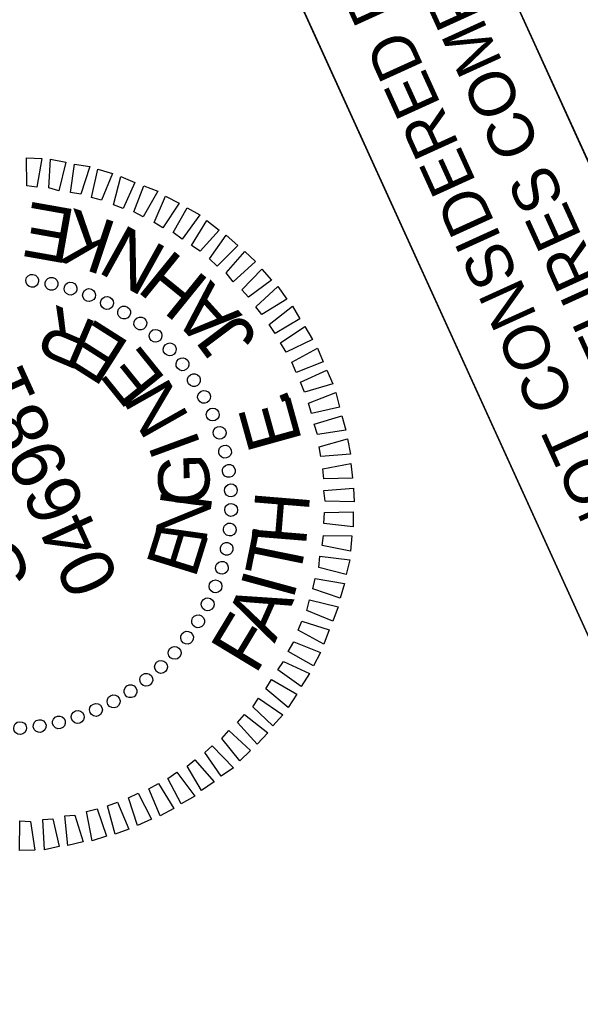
# Model space of a CAD drawing. Extents: x 2096093 to 2099001, y 683546 to 685907.
# Drawn here: x 2097494 to 2097556.6, y 685362.9 to 685471.3 of the extents above; entities that cross this region are included whole.
import ezdxf

# ---------------------------------------------------------------- set-up
doc = ezdxf.new("R2010")
doc.units = 0
for name, color, linetype in [('Old_Level_2', 7, 'Continuous'), ('Sheet Block Title CELL', 7, 'Continuous'), ('Sheet PE Seal Cell', 7, 'Continuous'), ('Sheet Sticker Exception Certification CELL', 7, 'Continuous')]:
    doc.layers.add(name, color=color, linetype=linetype)

msp = doc.modelspace()

# ---------------------------------------------------------------- linework, layer by layer
at = {"layer": 'Old_Level_2'}
msp.add_lwpolyline([(2097478.08, 685308.03), (2097400.68, 685478.2), (2097502.07, 685524.32), (2097579.47, 685354.15)], close=True, dxfattribs=at)
msp.add_lwpolyline([(2097478.08, 685308.03), (2097400.68, 685478.2), (2097502.07, 685524.32), (2097579.47, 685354.15)], close=True, dxfattribs=at)
at = {"layer": 'Sheet Block Title CELL'}
msp.add_lwpolyline([(2097599.44, 685363.23), (2097522.11, 685533.24), (2097544.43, 685543.38), (2097621.75, 685373.38)], close=True, dxfattribs=at)
at = {"layer": 'Sheet PE Seal Cell'}
for p, q in [((2097495.43, 685442.18), (2097495.43, 685442.18)), ((2097497.58, 685441.79), (2097497.58, 685441.79)), ((2097499.73, 685441.29), (2097499.73, 685441.29)), ((2097501.77, 685440.56), (2097501.77, 685440.56)), ((2097503.81, 685439.68), (2097503.81, 685439.68)), ((2097505.68, 685438.61), (2097505.68, 685438.61)), ((2097507.51, 685437.35), (2097507.51, 685437.35)), ((2097509.23, 685435.99), (2097509.23, 685435.99)), ((2097510.78, 685434.5), (2097510.78, 685434.5)), ((2097512.2, 685432.84), (2097512.2, 685432.84)), ((2097513.48, 685431), (2097513.48, 685431)), ((2097514.64, 685429.17), (2097514.64, 685429.17)), ((2097515.59, 685427.19), (2097515.59, 685427.19)), ((2097516.37, 685425.12), (2097516.37, 685425.12)), ((2097516.94, 685423.02), (2097516.94, 685423.02)), ((2097517.4, 685420.92), (2097517.4, 685420.92)), ((2097517.63, 685418.72), (2097517.63, 685418.72)), ((2097517.64, 685416.53), (2097517.64, 685416.53)), ((2097517.54, 685414.34), (2097517.54, 685414.34)), ((2097517.15, 685412.18), (2097517.15, 685412.18)), ((2097516.64, 685410.03), (2097516.64, 685410.03)), ((2097515.92, 685408), (2097515.92, 685408)), ((2097515.04, 685405.95), (2097515.04, 685405.95)), ((2097513.96, 685404.09), (2097513.96, 685404.09)), ((2097512.71, 685402.26), (2097512.71, 685402.26)), ((2097511.35, 685400.54), (2097511.35, 685400.54)), ((2097509.86, 685398.98), (2097509.86, 685398.98)), ((2097508.19, 685397.57), (2097508.19, 685397.57)), ((2097506.36, 685396.29), (2097506.36, 685396.29)), ((2097504.53, 685395.13), (2097504.53, 685395.13)), ((2097502.54, 685394.17), (2097502.54, 685394.17)), ((2097498.38, 685392.83), (2097498.38, 685392.83)), ((2097500.48, 685393.4), (2097500.48, 685393.4)), ((2097494.08, 685392.13), (2097494.08, 685392.13)), ((2097496.28, 685392.37), (2097496.28, 685392.37))]:
    msp.add_line(p, q, dxfattribs=at)
for points in [[(2097494.81, 685452.72), (2097494.77, 685455.84), (2097496.49, 685455.79), (2097495.92, 685452.57)], [(2097497.26, 685452.52), (2097497.47, 685455.69), (2097499.16, 685455.36), (2097498.41, 685452.17)], [(2097499.7, 685451.98), (2097500.13, 685455.15), (2097501.85, 685454.88), (2097500.84, 685451.79)], [(2097502.05, 685451.41), (2097502.75, 685454.58), (2097504.39, 685454.12), (2097503.16, 685451.14)], [(2097504.51, 685450.6), (2097505.32, 685453.77), (2097506.88, 685453.11), (2097505.57, 685450.2)], [(2097506.78, 685449.82), (2097507.88, 685452.73), (2097509.46, 685452.14), (2097507.81, 685449.25)], [(2097509.02, 685448.64), (2097510.32, 685451.59), (2097511.83, 685450.8), (2097510.01, 685448.05)], [(2097511.17, 685447.53), (2097512.73, 685450.27), (2097514.13, 685449.48), (2097512.18, 685446.78)], [(2097513.22, 685446.05), (2097514.91, 685448.85), (2097516.28, 685447.77), (2097514.16, 685445.43)], [(2097515.21, 685444.59), (2097517.09, 685447.2), (2097518.37, 685446.08), (2097516.07, 685443.77)], [(2097517.07, 685443.02), (2097519.17, 685445.41), (2097520.34, 685444.29), (2097517.86, 685442.01)], [(2097518.81, 685441.12), (2097521.07, 685443.41), (2097522.12, 685442.19), (2097519.57, 685440.31)], [(2097520.4, 685439.21), (2097522.83, 685441.47), (2097523.86, 685440.06), (2097521.06, 685438.35)], [(2097521.89, 685437.25), (2097524.48, 685439.3), (2097525.3, 685437.86), (2097522.53, 685436.22)], [(2097523.16, 685435.19), (2097525.85, 685437.01), (2097526.73, 685435.55), (2097523.79, 685434.16)], [(2097524.42, 685433.02), (2097527.28, 685434.59), (2097527.92, 685433.07), (2097524.88, 685431.9)], [(2097525.37, 685430.81), (2097528.33, 685432.16), (2097528.97, 685430.63), (2097525.82, 685429.7)], [(2097526.27, 685428.47), (2097529.31, 685429.64), (2097529.72, 685428.01), (2097526.59, 685427.3)], [(2097526.9, 685426.12), (2097530, 685427.04), (2097530.45, 685425.43), (2097527.26, 685424.97)], [(2097527.46, 685423.57), (2097530.62, 685424.47), (2097530.96, 685422.75), (2097527.66, 685422.52)], [(2097527.86, 685421.12), (2097530.99, 685421.72), (2097531.18, 685420.1), (2097527.97, 685420.02)], [(2097527.97, 685418.7), (2097531.31, 685418.96), (2097531.35, 685417.44), (2097528.13, 685417.51)], [(2097528.04, 685416.26), (2097531.24, 685416.34), (2097531.24, 685414.64), (2097527.99, 685415.03)], [(2097527.94, 685413.69), (2097531.09, 685413.64), (2097530.94, 685411.92), (2097527.79, 685412.58)], [(2097527.52, 685411.36), (2097530.88, 685410.96), (2097530.47, 685409.34), (2097527.43, 685410.11)], [(2097527, 685408.87), (2097530.27, 685408.32), (2097529.81, 685406.68), (2097526.76, 685407.71)], [(2097526.38, 685406.5), (2097529.59, 685405.71), (2097529, 685404.12), (2097526.09, 685405.32)], [(2097525.53, 685404.13), (2097528.56, 685403.15), (2097527.97, 685401.56), (2097525.11, 685403.12)], [(2097524.62, 685401.8), (2097527.62, 685400.63), (2097526.82, 685399.12), (2097524, 685400.74)], [(2097523.46, 685399.62), (2097526.39, 685398.26), (2097525.46, 685396.8), (2097522.85, 685398.68)], [(2097522.14, 685397.59), (2097524.96, 685395.97), (2097523.99, 685394.48), (2097521.52, 685396.54)], [(2097520.67, 685395.5), (2097523.42, 685393.67), (2097522.28, 685392.44), (2097520.06, 685394.56)], [(2097519.13, 685393.7), (2097521.72, 685391.63), (2097520.53, 685390.38), (2097518.33, 685392.79)], [(2097517.36, 685391.9), (2097519.81, 685389.67), (2097518.62, 685388.52), (2097516.61, 685391.01)], [(2097515.51, 685390.18), (2097517.88, 685387.75), (2097516.5, 685386.79), (2097514.7, 685389.43)], [(2097513.57, 685388.64), (2097515.74, 685386.17), (2097514.32, 685385.19), (2097512.74, 685387.93)], [(2097511.57, 685387.24), (2097513.56, 685384.57), (2097512.07, 685383.73), (2097510.56, 685386.56)], [(2097509.51, 685385.97), (2097511.22, 685383.18), (2097509.72, 685382.38), (2097508.46, 685385.38)], [(2097507.26, 685384.89), (2097508.74, 685382), (2097507.19, 685381.29), (2097506.17, 685384.39)], [(2097502.67, 685383.14), (2097503.73, 685380.1), (2097502.1, 685379.58), (2097501.48, 685382.87)], [(2097504.96, 685383.9), (2097506.22, 685380.9), (2097504.67, 685380.31), (2097503.83, 685383.5)], [(2097497.73, 685382.04), (2097498.43, 685378.95), (2097496.78, 685378.59), (2097496.61, 685381.97)], [(2097500.19, 685382.44), (2097501.11, 685379.46), (2097499.41, 685379.07), (2097499.07, 685382.37)], [(2097495.24, 685381.73), (2097495.7, 685378.54), (2097494.02, 685378.49), (2097494.05, 685381.8)]]:
    msp.add_lwpolyline(points, close=True, dxfattribs=at)
for centre, major_axis in [((2097495.42, 685442.12), (0.082, 0.715)), ((2097497.58, 685441.78), (0.144, 0.705)), ((2097499.7, 685441.25), (0.205, 0.69)), ((2097501.77, 685440.53), (0.264, 0.67)), ((2097503.77, 685439.64), (0.322, 0.644)), ((2097505.68, 685438.58), (0.377, 0.614)), ((2097507.49, 685437.36), (0.429, 0.578)), ((2097509.19, 685435.98), (0.477, 0.539)), ((2097510.77, 685434.46), (0.523, 0.495)), ((2097512.2, 685432.8), (0.564, 0.448)), ((2097513.48, 685431.03), (0.601, 0.397)), ((2097514.61, 685429.16), (0.633, 0.343)), ((2097515.57, 685427.19), (0.66, 0.287)), ((2097516.35, 685425.15), (0.683, 0.228)), ((2097516.95, 685423.04), (0.7, 0.168)), ((2097517.37, 685420.9), (0.712, 0.106)), ((2097517.6, 685418.72), (0.719, 0.043)), ((2097517.63, 685416.53), (0.72, -0.019)), ((2097517.48, 685414.35), (0.715, -0.082)), ((2097517.13, 685412.19), (0.705, -0.144)), ((2097516.6, 685410.07), (0.69, -0.205)), ((2097515.89, 685408), (0.67, -0.264)), ((2097515, 685406), (0.644, -0.322)), ((2097513.94, 685404.09), (0.614, -0.377)), ((2097512.71, 685402.27), (0.578, -0.429)), ((2097511.33, 685400.57), (0.539, -0.477)), ((2097509.81, 685399), (0.495, -0.523)), ((2097508.16, 685397.57), (0.448, -0.564)), ((2097506.39, 685396.28), (0.397, -0.601)), ((2097502.54, 685394.2), (0.287, -0.66)), ((2097504.51, 685395.16), (0.343, -0.633)), ((2097500.5, 685393.42), (0.228, -0.683)), ((2097494.07, 685392.17), (0.043, -0.719)), ((2097496.25, 685392.4), (0.106, -0.712)), ((2097498.4, 685392.81), (0.168, -0.7))]:
    msp.add_ellipse(centre, major_axis=major_axis, ratio=0.999708, dxfattribs=at)
at = {"layer": 'Sheet Sticker Exception Certification CELL'}
for p, q in [((2097522.11, 685533.24), (2097599.44, 685363.23)), ((2097522.11, 685533.24), (2097599.44, 685363.23)), ((2097579.47, 685354.15), (2097502.14, 685524.15)), ((2097579.47, 685354.15), (2097502.14, 685524.15))]:
    msp.add_line(p, q, dxfattribs=at)

# ---------------------------------------------------------------- texts
at = {"layer": 'Sheet PE Seal Cell'}
for s, height, rotation, p in [('E', 6.12, 169.951, (2097500.47, 685450.03)), ('K', 6.15, 161.6671, (2097505.12, 685448.55)), ('N', 6.14, 150.9413, (2097510.73, 685445.66)), ('H', 6.11, 140.9573, (2097515.39, 685442.08)), ('A', 6.06, 132.117, (2097518.94, 685438.28)), ('R', 5.78, 156.9394, (2097502.88, 685437.39)), ('E', 5.77, 147.5821, (2097506.49, 685435.13)), ('J', 6.03, 126.8591, (2097520.76, 685435.77)), ('E', 5.68, 128.8697, (2097510.46, 685431.11)), ('046981', 5.998, 114.458, (2097505.22, 685408.71)), ('N', 5.64, 119.5144, (2097513.05, 685426.86)), ('E', 6.02, 105.5157, (2097525.59, 685424.23)), ('.', 6, 112.625, (2097524.46, 685428.27)), ('SEAL', 5.998, 114.458, (2097495.43, 685408.85)), ('I', 5.64, 110.1592, (2097514.3, 685423.75)), ('G', 5.72, 91.4482, (2097515.29, 685417)), ('N', 5.76, 82.0919, (2097514.81, 685412.61)), ('H', 6.12, 85.3313, (2097525.98, 685412.41)), ('E', 5.78, 72.7349, (2097513.6, 685408.76)), ('T', 6.14, 78.5311, (2097525.18, 685408.48)), ('I', 6.15, 74.7291, (2097524.53, 685406.34)), ('A', 6.15, 65.8888, (2097522.48, 685401.56)), ('F', 6.12, 58.8722, (2097520.34, 685398.02))]:
    msp.add_text(s, height=height, rotation=rotation, dxfattribs=at).set_placement(p)
at = {"layer": 'Sheet Sticker Exception Certification CELL'}
for s, p in [('UNLESS ALL SIGNATURES COMPLETED', (2097589.55, 685375.15)), ('UNLESS ALL SIGNATURES COMPLETED', (2097589.55, 685375.15)), ('DOCUMENT NOT CONSIDERED FINAL', (2097580.11, 685376.05)), ('DOCUMENT NOT CONSIDERED FINAL', (2097580.11, 685376.05))]:
    msp.add_text(s, height=5.135, rotation=114.458, dxfattribs=at).set_placement(p)

doc.saveas('drawing.dxf')
